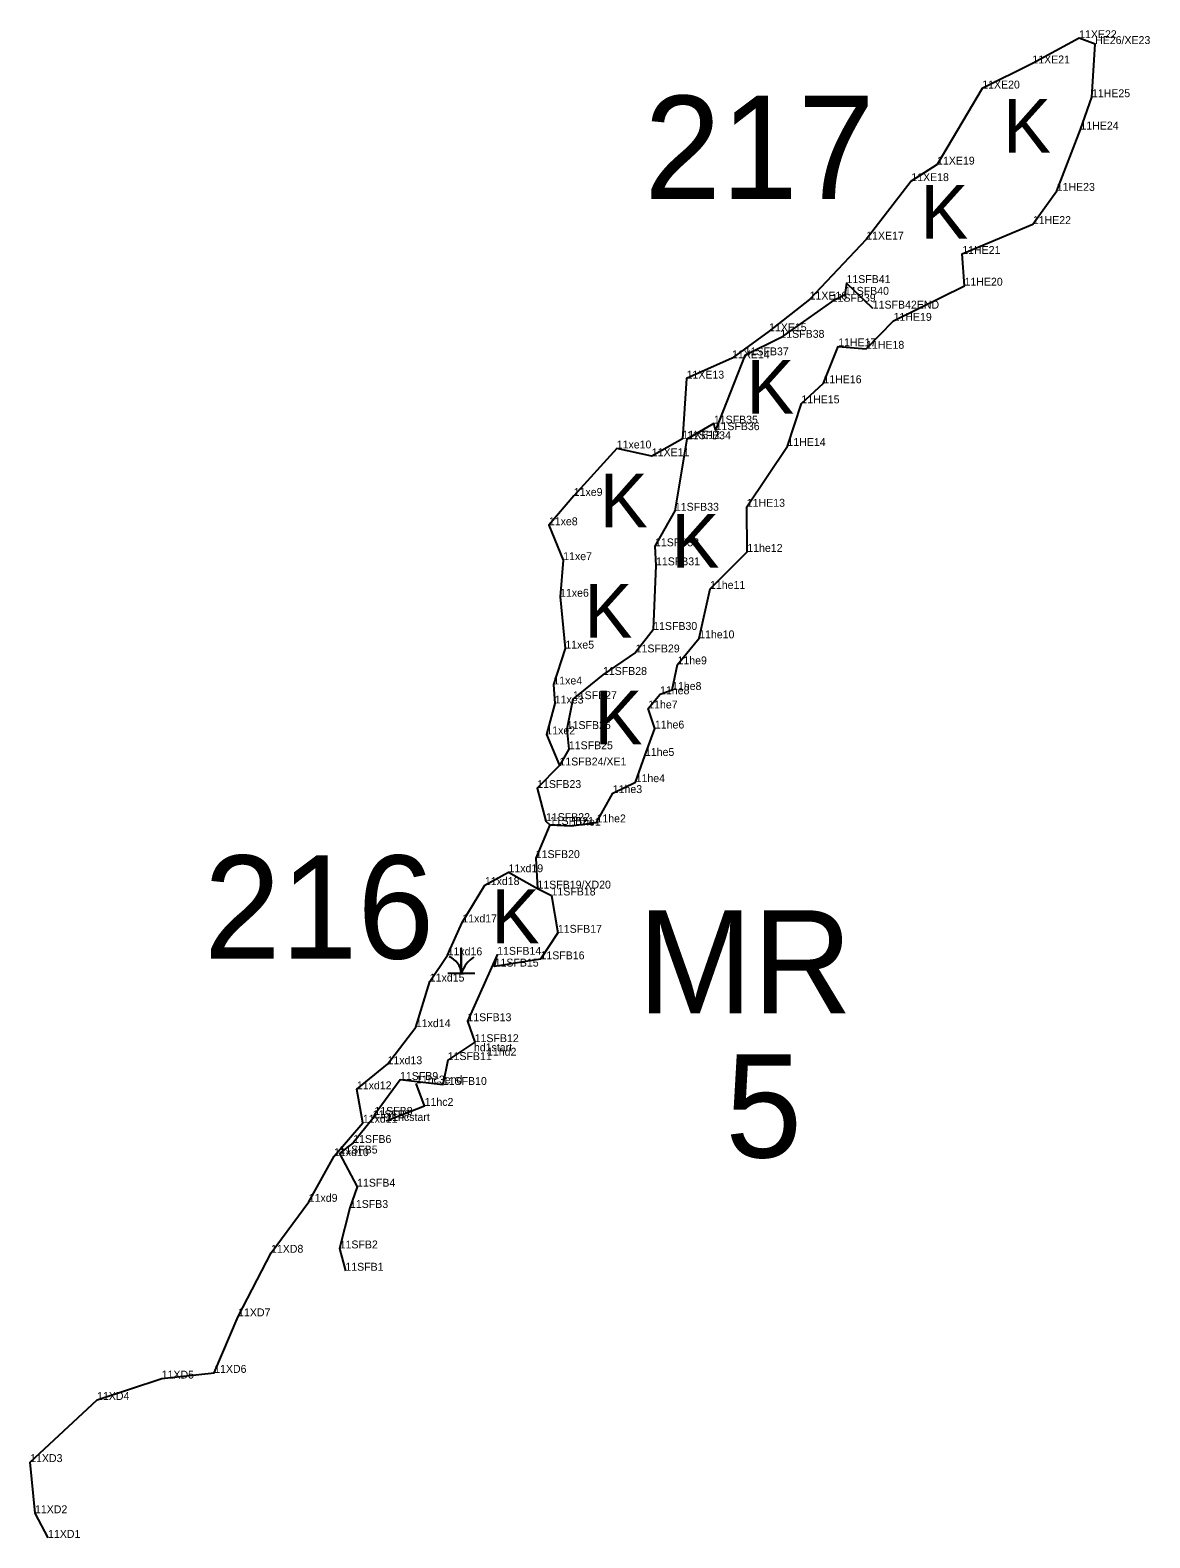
# Model space of a CAD drawing. Extents: x 2072529 to 2268796, y 436423 to 470406.
# Drawn here: x 2235708 to 2236417, y 448547 to 449501 of the extents above; entities that cross this region are included whole.
import ezdxf

# ---------------------------------------------------------------- set-up
doc = ezdxf.new("R2010")
doc.units = 0
for name, color, linetype in [('Default', 7, 'Continuous'), ('Exist Environmental Wetland Boundary', 7, 'Continuous'), ('Exist Environmental Wetland Boundary Cogo Comment', 7, 'Continuous'), ('Exist Hydro Jurisdictional Stream or Body of Water NEU Mitigable', 7, 'Continuous'), ('Exist Hydro Jurisdictional Stream or Body of Water NEU Mitigable Cogo Comment', 7, 'Continuous'), ('Exist Hydro Swamp or Marsh', 7, 'Continuous'), ('Old_Level_20', 7, 'Continuous')]:
    doc.layers.add(name, color=color, linetype=linetype)

msp = doc.modelspace()

# ---------------------------------------------------------------- linework, layer by layer
at = {"layer": 'Exist Environmental Wetland Boundary'}
for points in [[(2236037.3, 448998.13), (2236050.89, 448997.62), (2236066.83, 448999.71), (2236077.13, 449018.28), (2236091.62, 449025.2), (2236097.5, 449041.82), (2236103.8, 449059.16), (2236099.57, 449071.87), (2236107.06, 449080.86), (2236114.67, 449083.57), (2236118.11, 449099.8), (2236131.84, 449116.29), (2236138.7, 449147.6), (2236162.29, 449171.03), (2236161.99, 449199.61), (2236187.7, 449238.09), (2236196.53, 449265.11), (2236210.46, 449277.84), (2236219.85, 449301.21), (2236237.49, 449299.69), (2236254.91, 449317.39), (2236299.83, 449339.64), (2236298.38, 449359.71), (2236343.07, 449378.68), (2236358.18, 449399.71), (2236373.23, 449438.55), (2236380.5, 449459.03), (2236382.49, 449492.67), (2236372.38, 449496.4), (2236342.77, 449480.41), (2236311.04, 449464.52), (2236282.46, 449416.33), (2236266.13, 449405.87), (2236237.58, 449368.84), (2236201.73, 449330.85), (2236176.08, 449310.81), (2236152.63, 449293.63), (2236123.87, 449280.79), (2236121.29, 449242.72), (2236101.84, 449231.63), (2236079.64, 449236.55), (2236052.42, 449206.47), (2236036.69, 449187.89), (2236045.75, 449165.81), (2236043.75, 449142.63), (2236047.07, 449109.75), (2236039.52, 449087.06), (2236040.41, 449075.01), (2236035.09, 449055.46), (2236043.38, 449035.76)], [(2235719.64, 448546.57), (2235711.36, 448562.16), (2235708.3, 448594.57), (2235750.67, 448633.92), (2235791.56, 448647.47), (2235824.79, 448651.08), (2235839.96, 448686.86), (2235860.77, 448727.14), (2235884.65, 448759.4), (2235900.69, 448788.37), (2235918.94, 448809.49), (2235915.15, 448830.66), (2235934.55, 448846.56), (2235952.48, 448870.04), (2235961.3, 448898.91), (2235972.58, 448915.52), (2235981.89, 448936.38), (2235996.15, 448960.02), (2236011.12, 448968.15), (2236029.48, 448957.79)], [(2235933.77, 448810.61), (2235958.04, 448820.17), (2235952.66, 448834.37)]]:
    msp.add_lwpolyline(points, dxfattribs=at)
at = {"layer": 'Exist Hydro Jurisdictional Stream or Body of Water NEU Mitigable'}
msp.add_lwpolyline([(2236241.74, 449325.11), (2236225.1, 449341.31), (2236224.09, 449333.87), (2236215.69, 449329.47), (2236183.26, 449306.62), (2236160.65, 449295.51), (2236142.22, 449248.15), (2236141.13, 449252.27), (2236124.03, 449242.41), (2236116.45, 449197.09), (2236103.85, 449174.58), (2236104.49, 449162.51), (2236102.72, 449121.6), (2236091.62, 449107.36), (2236070.91, 449093.11), (2236051.87, 449077.76), (2236047.98, 449058.84), (2236049.33, 449046.04), (2236043.38, 449035.76), (2236029.27, 449021.48), (2236034.82, 449000.54), (2236037.3, 448998.13), (2236028.4, 448977.1), (2236029.48, 448957.79), (2236038.37, 448953.43), (2236042.39, 448929.8), (2236031.38, 448912.99), (2236002.33, 448908.41), (2236003.96, 448915.84), (2235985.1, 448873.81), (2235989.7, 448860.53), (2235972.62, 448849.17), (2235969.54, 448833.42), (2235942.44, 448836.6), (2235926.24, 448814.48), (2235925.16, 448812.27), (2235912.81, 448796.67), (2235904.11, 448789.98), (2235915.28, 448768.98), (2235910.77, 448755.52), (2235904.23, 448729.89), (2235907.85, 448715.76)], dxfattribs=at)
at = {"layer": 'Exist Hydro Swamp or Marsh'}
msp.add_lwpolyline([(2235972.62, 448904.18), (2235981.22, 448904.18), (2235981.22, 448919.96), (2235981.22, 448904.18), (2235989.82, 448904.18)], dxfattribs=at)
for centre, radius, start, end in [((2235968.95, 448903.29), 12.3, 4.14034, 67.53497), ((2235999.46, 448898.12), 19.22, 122.12745, 161.62219)]:
    msp.add_arc(centre, radius, start, end, dxfattribs=at)
at = {"layer": 'Old_Level_20'}
for p, q in [((2236372.38, 449496.4), (2236372.38, 449496.4)), ((2236382.49, 449492.67), (2236382.49, 449492.67)), ((2236342.77, 449480.41), (2236342.77, 449480.41)), ((2236311.04, 449464.52), (2236311.04, 449464.52)), ((2236380.5, 449459.03), (2236380.5, 449459.03)), ((2236373.23, 449438.55), (2236373.23, 449438.55)), ((2236282.46, 449416.33), (2236282.46, 449416.33)), ((2236266.13, 449405.87), (2236266.13, 449405.87)), ((2236358.18, 449399.71), (2236358.18, 449399.71)), ((2236343.07, 449378.68), (2236343.07, 449378.68)), ((2236237.58, 449368.84), (2236237.58, 449368.84)), ((2236298.38, 449359.71), (2236298.38, 449359.71)), ((2236225.1, 449341.31), (2236225.1, 449341.31)), ((2236299.83, 449339.64), (2236299.83, 449339.64)), ((2236201.73, 449330.85), (2236201.73, 449330.85)), ((2236224.09, 449333.87), (2236224.09, 449333.87)), ((2236215.69, 449329.47), (2236215.69, 449329.47)), ((2236241.74, 449325.11), (2236241.74, 449325.11)), ((2236176.08, 449310.81), (2236176.08, 449310.81)), ((2236254.91, 449317.39), (2236254.91, 449317.39)), ((2236183.26, 449306.62), (2236183.26, 449306.62)), ((2236219.85, 449301.21), (2236219.85, 449301.21)), ((2236152.63, 449293.63), (2236152.63, 449293.63)), ((2236160.65, 449295.51), (2236160.65, 449295.51)), ((2236237.49, 449299.69), (2236237.49, 449299.69)), ((2236123.87, 449280.79), (2236123.87, 449280.79)), ((2236210.46, 449277.84), (2236210.46, 449277.84)), ((2236196.53, 449265.11), (2236196.53, 449265.11)), ((2236141.13, 449252.27), (2236141.13, 449252.27)), ((2236142.22, 449248.15), (2236142.22, 449248.15)), ((2236079.64, 449236.55), (2236079.64, 449236.55)), ((2236121.29, 449242.72), (2236121.29, 449242.72)), ((2236124.03, 449242.41), (2236124.03, 449242.41)), ((2236187.7, 449238.09), (2236187.7, 449238.09)), ((2236101.84, 449231.63), (2236101.84, 449231.63)), ((2236052.42, 449206.47), (2236052.42, 449206.47)), ((2236116.45, 449197.09), (2236116.45, 449197.09)), ((2236161.99, 449199.61), (2236161.99, 449199.61)), ((2236036.69, 449187.89), (2236036.69, 449187.89)), ((2236103.85, 449174.58), (2236103.85, 449174.58)), ((2236162.29, 449171.03), (2236162.29, 449171.03)), ((2236045.75, 449165.81), (2236045.75, 449165.81)), ((2236104.49, 449162.51), (2236104.49, 449162.51)), ((2236043.75, 449142.63), (2236043.75, 449142.63)), ((2236138.7, 449147.6), (2236138.7, 449147.6)), ((2236102.72, 449121.6), (2236102.72, 449121.6)), ((2236131.84, 449116.29), (2236131.84, 449116.29)), ((2236047.07, 449109.75), (2236047.07, 449109.75)), ((2236091.62, 449107.36), (2236091.62, 449107.36)), ((2236070.91, 449093.11), (2236070.91, 449093.11)), ((2236118.11, 449099.8), (2236118.11, 449099.8)), ((2236039.52, 449087.06), (2236039.52, 449087.06)), ((2236114.67, 449083.57), (2236114.67, 449083.57)), ((2236040.41, 449075.01), (2236040.41, 449075.01)), ((2236051.87, 449077.76), (2236051.87, 449077.76)), ((2236107.06, 449080.86), (2236107.06, 449080.86)), ((2236099.57, 449071.87), (2236099.57, 449071.87)), ((2236035.09, 449055.46), (2236035.09, 449055.46)), ((2236047.98, 449058.84), (2236047.98, 449058.84)), ((2236103.8, 449059.16), (2236103.8, 449059.16)), ((2236049.33, 449046.04), (2236049.33, 449046.04)), ((2236043.38, 449035.76), (2236043.38, 449035.76)), ((2236043.38, 449035.76), (2236043.38, 449035.76)), ((2236097.5, 449041.82), (2236097.5, 449041.82)), ((2236091.62, 449025.2), (2236091.62, 449025.2)), ((2236029.27, 449021.48), (2236029.27, 449021.48)), ((2236077.13, 449018.28), (2236077.13, 449018.28)), ((2236034.82, 449000.54), (2236034.82, 449000.54)), ((2236037.3, 448998.13), (2236037.3, 448998.13)), ((2236050.89, 448997.62), (2236050.89, 448997.62)), ((2236066.83, 448999.71), (2236066.83, 448999.71)), ((2236028.4, 448977.1), (2236028.4, 448977.1)), ((2236011.12, 448968.15), (2236011.12, 448968.15)), ((2235996.15, 448960.02), (2235996.15, 448960.02)), ((2236029.48, 448957.79), (2236029.48, 448957.79)), ((2236029.48, 448957.79), (2236029.48, 448957.79)), ((2236038.37, 448953.43), (2236038.37, 448953.43)), ((2235981.89, 448936.38), (2235981.89, 448936.38)), ((2236042.39, 448929.8), (2236042.39, 448929.8)), ((2235972.58, 448915.52), (2235972.58, 448915.52)), ((2236003.96, 448915.84), (2236003.96, 448915.84)), ((2236031.38, 448912.99), (2236031.38, 448912.99)), ((2236002.33, 448908.41), (2236002.33, 448908.41)), ((2235961.3, 448898.91), (2235961.3, 448898.91)), ((2235985.1, 448873.81), (2235985.1, 448873.81)), ((2235952.48, 448870.04), (2235952.48, 448870.04)), ((2235989.23, 448854.75), (2235989.23, 448854.75)), ((2235989.7, 448860.53), (2235989.7, 448860.53)), ((2235934.55, 448846.56), (2235934.55, 448846.56)), ((2235972.62, 448849.17), (2235972.62, 448849.17)), ((2235997.53, 448851.96), (2235997.53, 448851.96)), ((2235942.44, 448836.6), (2235942.44, 448836.6)), ((2235952.66, 448834.37), (2235952.66, 448834.37)), ((2235969.54, 448833.42), (2235969.54, 448833.42)), ((2235915.15, 448830.66), (2235915.15, 448830.66)), ((2235926.24, 448814.48), (2235926.24, 448814.48)), ((2235958.04, 448820.17), (2235958.04, 448820.17)), ((2235918.94, 448809.49), (2235918.94, 448809.49)), ((2235925.16, 448812.27), (2235925.16, 448812.27)), ((2235933.77, 448810.61), (2235933.77, 448810.61)), ((2235912.81, 448796.67), (2235912.81, 448796.67)), ((2235900.69, 448788.37), (2235900.69, 448788.37)), ((2235904.11, 448789.98), (2235904.11, 448789.98)), ((2235915.28, 448768.98), (2235915.28, 448768.98)), ((2235884.65, 448759.4), (2235884.65, 448759.4)), ((2235910.77, 448755.52), (2235910.77, 448755.52)), ((2235904.23, 448729.89), (2235904.23, 448729.89)), ((2235860.77, 448727.14), (2235860.77, 448727.14)), ((2235907.85, 448715.76), (2235907.85, 448715.76)), ((2235839.96, 448686.86), (2235839.96, 448686.86)), ((2235791.56, 448647.47), (2235791.56, 448647.47)), ((2235824.79, 448651.08), (2235824.79, 448651.08)), ((2235750.67, 448633.92), (2235750.67, 448633.92)), ((2235708.3, 448594.57), (2235708.3, 448594.57)), ((2235711.36, 448562.16), (2235711.36, 448562.16)), ((2235719.64, 448546.57), (2235719.64, 448546.57))]:
    msp.add_line(p, q, dxfattribs=at)

# ---------------------------------------------------------------- texts
at = {"layer": 'Default'}
for s, p in [('217', (2236097.06, 449394.6)), ('216', (2235818.3, 448913.41)), ('MR', (2236092.84, 448878.69)), ('5', (2236148.37, 448787.47))]:
    msp.add_text(s, height=65.34, dxfattribs=at).set_placement(p)
at = {"layer": 'Exist Environmental Wetland Boundary Cogo Comment'}
for s, p in [('11XE22', (2236372.38, 449496.4)), ('HE26/XE23', (2236382.49, 449492.67)), ('11XE21', (2236342.77, 449480.41)), ('11XE20', (2236311.04, 449464.52)), ('11HE25', (2236380.5, 449459.03)), ('11HE24', (2236373.23, 449438.55)), ('11XE19', (2236282.46, 449416.33)), ('11XE18', (2236266.13, 449405.87)), ('11HE23', (2236358.18, 449399.71)), ('11HE22', (2236343.07, 449378.68)), ('11XE17', (2236237.58, 449368.84)), ('11HE21', (2236298.38, 449359.71)), ('11HE20', (2236299.83, 449339.64)), ('11XE16', (2236201.73, 449330.85)), ('11SFB42END', (2236241.74, 449325.11)), ('11HE19', (2236254.91, 449317.39)), ('11XE15', (2236176.08, 449310.81)), ('11HE17', (2236219.85, 449301.21)), ('11HE18', (2236237.49, 449299.69)), ('11XE14', (2236152.63, 449293.63)), ('11XE13', (2236123.87, 449280.79)), ('11HE16', (2236210.46, 449277.84)), ('11HE15', (2236196.53, 449265.11)), ('11XE12', (2236121.29, 449242.72)), ('11xe10', (2236079.64, 449236.55)), ('11XE11', (2236101.84, 449231.63)), ('11HE14', (2236187.7, 449238.09)), ('11xe9', (2236052.42, 449206.47)), ('11HE13', (2236161.99, 449199.61)), ('11xe8', (2236036.69, 449187.89)), ('11xe7', (2236045.75, 449165.81)), ('11he12', (2236162.29, 449171.03)), ('11he11', (2236138.7, 449147.6)), ('11xe6', (2236043.75, 449142.63)), ('11he10', (2236131.84, 449116.29)), ('11xe5', (2236047.07, 449109.75)), ('11he9', (2236118.11, 449099.8)), ('11xe4', (2236039.52, 449087.06)), ('11he8', (2236107.06, 449080.86)), ('11he8', (2236114.67, 449083.57)), ('11xe3', (2236040.41, 449075.01)), ('11he7', (2236099.57, 449071.87)), ('11he6', (2236103.8, 449059.16)), ('11xe2', (2236035.09, 449055.46)), ('11he5', (2236097.5, 449041.82)), ('11he4', (2236091.62, 449025.2)), ('11he3', (2236077.13, 449018.28)), ('11he1', (2236050.89, 448997.62)), ('11he2', (2236066.83, 448999.71)), ('11xd19', (2236011.12, 448968.15)), ('11xd18', (2235996.15, 448960.02)), ('11xd17', (2235981.89, 448936.38)), ('11xd16', (2235972.58, 448915.52)), ('11xd15', (2235961.3, 448898.91)), ('11xd14', (2235952.48, 448870.04)), ('11xd13', (2235934.55, 448846.56)), ('11xd12', (2235915.15, 448830.66)), ('11xd11', (2235918.94, 448809.49)), ('11xd10', (2235900.69, 448788.37)), ('11xd9', (2235884.65, 448759.4)), ('11XD8', (2235860.77, 448727.14)), ('11XD7', (2235839.96, 448686.86)), ('11XD5', (2235791.56, 448647.47)), ('11XD6', (2235824.79, 448651.08)), ('11XD4', (2235750.67, 448633.92)), ('11XD3', (2235708.3, 448594.57)), ('11XD2', (2235711.36, 448562.16)), ('11XD1', (2235719.64, 448546.57))]:
    msp.add_text(s, height=5, dxfattribs=at).set_placement(p)
at = {"layer": 'Exist Hydro Jurisdictional Stream or Body of Water NEU Mitigable Cogo Comment'}
for s, p in [('11SFB41', (2236225.1, 449341.31)), ('11SFB39', (2236215.69, 449329.47)), ('11SFB40', (2236224.09, 449333.87)), ('11SFB38', (2236183.26, 449306.62)), ('11SFB37', (2236160.65, 449295.51)), ('11SFB35', (2236141.13, 449252.27)), ('11SFB34', (2236124.03, 449242.41)), ('11SFB36', (2236142.22, 449248.15)), ('11SFB33', (2236116.45, 449197.09)), ('11SFB32', (2236103.85, 449174.58)), ('11SFB31', (2236104.49, 449162.51)), ('11SFB30', (2236102.72, 449121.6)), ('11SFB29', (2236091.62, 449107.36)), ('11SFB28', (2236070.91, 449093.11)), ('11SFB27', (2236051.87, 449077.76)), ('11SFB26', (2236047.98, 449058.84)), ('11SFB25', (2236049.33, 449046.04)), ('11SFB24/XE1', (2236043.38, 449035.76)), ('11SFB23', (2236029.27, 449021.48)), ('11SFB22', (2236034.82, 449000.54)), ('11SFB21', (2236037.3, 448998.13)), ('11SFB20', (2236028.4, 448977.1)), ('11SFB19/XD20', (2236029.48, 448957.79)), ('11SFB18', (2236038.37, 448953.43)), ('11SFB17', (2236042.39, 448929.8)), ('11SFB14', (2236003.96, 448915.84)), ('11SFB15', (2236002.33, 448908.41)), ('11SFB16', (2236031.38, 448912.99)), ('11SFB13', (2235985.1, 448873.81)), ('11SFB12', (2235989.7, 448860.53)), ('11SFB11', (2235972.62, 448849.17)), ('hd1start', (2235989.23, 448854.75)), ('11hd2', (2235997.53, 448851.96)), ('11SFB9', (2235942.44, 448836.6)), ('11hc3end', (2235952.58, 448834.35)), ('11SFB10', (2235969.54, 448833.42)), ('11hc2', (2235958.04, 448820.17)), ('11SFB7', (2235925.16, 448812.27)), ('11SFB8', (2235926.24, 448814.48)), ('11hcstart', (2235933.77, 448810.61)), ('11SFB6', (2235912.81, 448796.67)), ('11SFB5', (2235904.11, 448789.98)), ('11SFB4', (2235915.28, 448768.98)), ('11SFB3', (2235910.77, 448755.52)), ('11SFB2', (2235904.23, 448729.89)), ('11SFB1', (2235907.85, 448715.76))]:
    msp.add_text(s, height=5, dxfattribs=at).set_placement(p)
at = {"layer": 'Exist Hydro Swamp or Marsh'}
for p in [(2236324.27, 449423.8), (2236271.86, 449369.37), (2236161.67, 449258.5), (2236068.94, 449186.61), (2236114.3, 449161.07), (2236059.2, 449116.73), (2236065.58, 449049.2), (2236000.4, 448923.21)]:
    msp.add_text('K', height=34, dxfattribs=at).set_placement(p)

doc.saveas('drawing.dxf')
